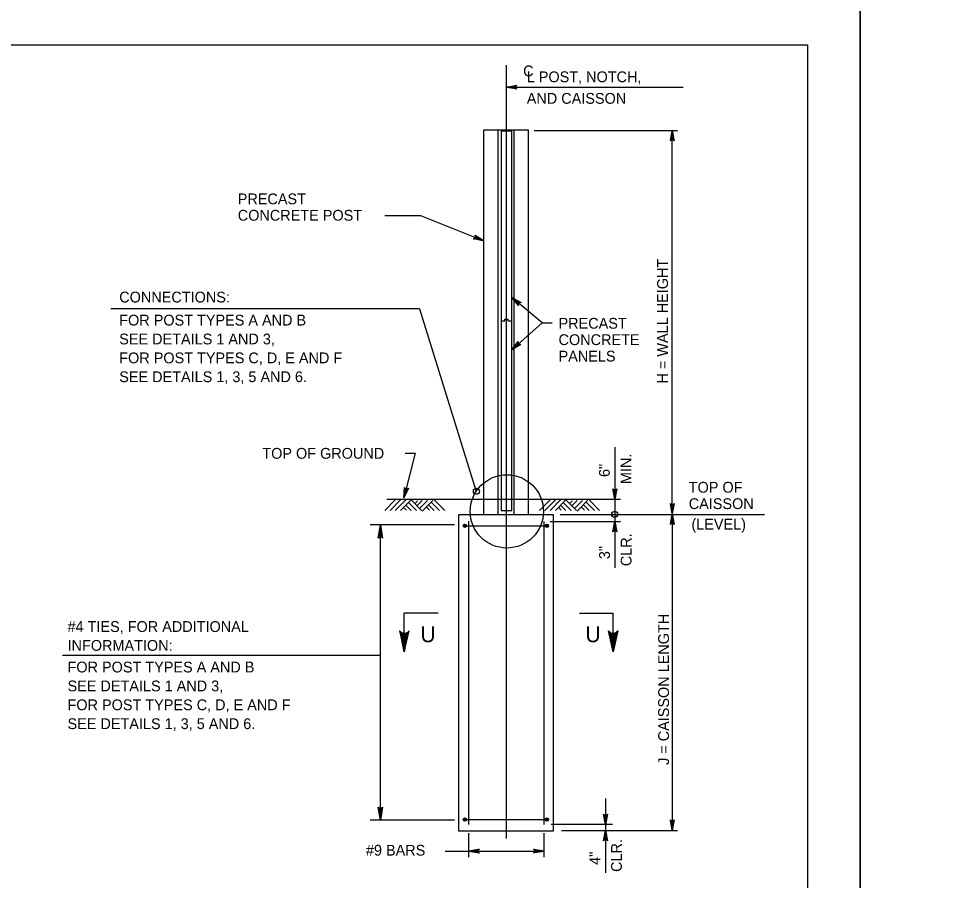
# Model space of a CAD drawing. Extents: x 3351 to 8430, y -3586 to 1457.
# Drawn here: x 4362.8 to 4626.6, y -3245.2 to -2999.8 of the extents above; entities that cross this region are included whole.
import ezdxf

# ---------------------------------------------------------------- set-up
doc = ezdxf.new("R2010")
doc.units = 0
for name, color, linetype in [('1', 7, 'Continuous'), ('2', 7, 'Continuous'), ('PLT-BNDY', 7, 'Continuous')]:
    doc.layers.add(name, color=color, linetype=linetype)

msp = doc.modelspace()

# ---------------------------------------------------------------- linework, layer by layer
at = {"layer": '1'}
for p, q in [((4501.69, -3233.31), (4501.69, -3013.08)), ((4501.69, -3019.37), (4551.98, -3019.37)), ((4495.23, -3141), (4495.23, -3031.53)), ((4495.23, -3031.53), (4507.98, -3031.53)), ((4499.36, -3141), (4499.36, -3031.53)), ((4503.86, -3141), (4503.86, -3031.53)), ((4507.98, -3141), (4507.98, -3031.53)), ((4509.59, -3031.69), (4550.39, -3031.69)), ((4548.88, -3140.87), (4548.88, -3031.69)), ((4467.06, -3055.93), (4477.25, -3055.93)), ((4477.25, -3055.93), (4495.23, -3063.11)), ((4511.82, -3086.41), (4503.19, -3079.21)), ((4476.92, -3082.48), (4389.09, -3082.48)), ((4476.92, -3082.48), (4493.06, -3134.45)), ((4500.19, -3085.91), (4500.19, -3103.66)), ((4501.21, -3085.91), (4501.21, -3085.43)), ((4501.21, -3085.43), (4502.17, -3085.43)), ((4502.17, -3085.91), (4502.17, -3085.43)), ((4503.19, -3103.35), (4503.19, -3085.91)), ((4511.82, -3086.41), (4503.19, -3094.16)), ((4511.82, -3086.41), (4514.72, -3086.41)), ((4532.5, -3121.82), (4532.5, -3141)), ((4475.72, -3123.53), (4472.5, -3136.33)), ((4472.82, -3123.53), (4475.72, -3123.53)), ((4467.05, -3139.89), (4470.05, -3136.89)), ((4467.68, -3136.68), (4534.14, -3136.68)), ((4468.55, -3139.89), (4471.55, -3136.89)), ((4470.05, -3139.89), (4473.05, -3136.89)), ((4471.55, -3139.89), (4474.55, -3136.89)), ((4473.22, -3139.83), (4472.4, -3139.01)), ((4474.55, -3139.89), (4473.05, -3138.39)), ((4476.05, -3139.89), (4473.8, -3137.64)), ((4477.55, -3139.89), (4474.55, -3136.89)), ((4476.4, -3137.12), (4475.58, -3137.95)), ((4477.73, -3137.07), (4476.22, -3138.57)), ((4479.23, -3137.07), (4476.97, -3139.32)), ((4480.73, -3137.07), (4477.72, -3140.07)), ((4479.81, -3139.83), (4478.99, -3139.01)), ((4481.14, -3139.89), (4479.64, -3138.39)), ((4482.64, -3139.89), (4480.39, -3137.64)), ((4484.14, -3139.89), (4481.14, -3136.89)), ((4511.11, -3139.86), (4514.11, -3136.86)), ((4512.61, -3139.86), (4515.61, -3136.86)), ((4514.11, -3139.86), (4517.11, -3136.86)), ((4515.61, -3139.86), (4518.61, -3136.86)), ((4517.28, -3139.8), (4516.46, -3138.98)), ((4518.61, -3139.86), (4517.11, -3138.36)), ((4520.11, -3139.86), (4517.86, -3137.61)), ((4521.61, -3139.86), (4518.61, -3136.86)), ((4520.46, -3137.09), (4519.64, -3137.92)), ((4521.79, -3137.04), (4520.29, -3138.54)), ((4523.29, -3137.04), (4521.04, -3139.29)), ((4524.79, -3137.04), (4521.79, -3140.04)), ((4523.87, -3139.8), (4523.05, -3138.98)), ((4525.2, -3139.86), (4523.7, -3138.36)), ((4526.7, -3139.86), (4524.45, -3137.61)), ((4528.2, -3139.86), (4525.2, -3136.86)), ((4515.07, -3141.12), (4488.07, -3141.12)), ((4488.07, -3141.12), (4488.07, -3231.12)), ((4515.07, -3231.12), (4515.07, -3141.12)), ((4516.94, -3141), (4575.13, -3141)), ((4532.5, -3141), (4532.5, -3143)), ((4548.88, -3140.87), (4548.88, -3230.97)), ((4486.92, -3144), (4462.89, -3144)), ((4465.22, -3147.74), (4465.81, -3143.94)), ((4465.81, -3143.94), (4465.38, -3147.54)), ((4465.64, -3147.41), (4465.81, -3143.94)), ((4465.81, -3228.12), (4465.81, -3143.94)), ((4465.81, -3143.94), (4466, -3147.41)), ((4466.27, -3147.53), (4465.81, -3143.94)), ((4465.81, -3143.94), (4466.44, -3147.73)), ((4465.81, -3143.94), (4465.82, -3147.41)), ((4489.87, -3144.22), (4513.2, -3144.22)), ((4491.01, -3229.33), (4491.01, -3142.94)), ((4512.37, -3229.33), (4512.37, -3143)), ((4514.1, -3143), (4534.14, -3143)), ((4532.5, -3143), (4532.5, -3156.19)), ((4465.38, -3147.54), (4465.22, -3147.74)), ((4465.38, -3147.54), (4465.64, -3147.41)), ((4465.64, -3147.41), (4466, -3147.41)), ((4466, -3147.41), (4466.27, -3147.53)), ((4466.44, -3147.73), (4466.27, -3147.53)), ((4482.21, -3169.1), (4472.56, -3169.1)), ((4472.56, -3180.1), (4472.56, -3169.1)), ((4522.44, -3169.1), (4532.09, -3169.1)), ((4532.09, -3180.1), (4532.09, -3169.1)), ((4465.81, -3181.14), (4375.38, -3181.14)), ((4529.87, -3221.92), (4529.87, -3229.33)), ((4465.81, -3228.12), (4465.17, -3224.33)), ((4465.17, -3224.33), (4465.35, -3224.52)), ((4465.61, -3224.65), (4465.35, -3224.52)), ((4465.35, -3224.52), (4465.81, -3228.12)), ((4465.81, -3228.12), (4465.61, -3224.65)), ((4465.97, -3224.65), (4465.61, -3224.65)), ((4465.81, -3228.12), (4465.79, -3224.65)), ((4466.4, -3224.32), (4465.81, -3228.12)), ((4465.81, -3228.12), (4466.24, -3224.51)), ((4465.97, -3224.65), (4465.81, -3228.12)), ((4466.24, -3224.51), (4465.97, -3224.65)), ((4466.24, -3224.51), (4466.4, -3224.32)), ((4486.92, -3228.08), (4462.89, -3228.08)), ((4489.87, -3227.9), (4513.2, -3227.9)), ((4488.07, -3231.12), (4515.07, -3231.12)), ((4531.87, -3229.33), (4514.37, -3229.33)), ((4517.37, -3230.97), (4550.39, -3230.97)), ((4529.87, -3229.33), (4529.87, -3230.97)), ((4529.87, -3230.97), (4529.87, -3243.06)), ((4491.01, -3238.56), (4491.01, -3231.77)), ((4512.37, -3238.56), (4512.37, -3231.77)), ((4484.22, -3236.85), (4491.01, -3236.85)), ((4491.01, -3236.85), (4512.37, -3236.85))]:
    msp.add_line(p, q, dxfattribs=at)
for points in [[(4501.69, -3019.37), (4504.68, -3018.81), (4504.45, -3018.97), (4504.33, -3019.17), (4504.29, -3019.37), (4504.33, -3019.57), (4504.45, -3019.77), (4504.68, -3019.93), (4501.69, -3019.37), (4504.45, -3019.77), (4504.33, -3019.57), (4501.69, -3019.37), (4504.29, -3019.37), (4504.33, -3019.17), (4501.69, -3019.37), (4504.45, -3018.97)], [(4503.19, -3049.61), (4503.19, -3031.91), (4500.19, -3031.91), (4500.19, -3050.4)], [(4548.88, -3031.69), (4549.44, -3034.67), (4549.36, -3034.55), (4549.28, -3034.44), (4549.18, -3034.38), (4549.08, -3034.32), (4548.98, -3034.3), (4548.88, -3034.29), (4548.78, -3034.3), (4548.68, -3034.32), (4548.58, -3034.38), (4548.48, -3034.44), (4548.4, -3034.55), (4548.32, -3034.67), (4548.88, -3031.69), (4548.4, -3034.55), (4548.48, -3034.44), (4548.88, -3031.69), (4548.58, -3034.38), (4548.68, -3034.32), (4548.88, -3031.69), (4548.78, -3034.3), (4548.88, -3034.29), (4548.88, -3031.69), (4548.98, -3034.3), (4549.08, -3034.32), (4548.88, -3031.69), (4549.18, -3034.38), (4549.28, -3034.44), (4548.88, -3031.69), (4549.36, -3034.55)], [(4500.19, -3050.09), (4500.19, -3067.91)], [(4503.19, -3085.91), (4503.19, -3049.34)], [(4495.23, -3063.11), (4492.25, -3062.52), (4492.39, -3062.49), (4492.53, -3062.46), (4492.62, -3062.39), (4492.71, -3062.32), (4492.76, -3062.23), (4492.82, -3062.14), (4492.84, -3062.04), (4492.86, -3061.95), (4492.84, -3061.83), (4492.82, -3061.72), (4492.75, -3061.6), (4492.67, -3061.48), (4495.23, -3063.11), (4492.75, -3061.6), (4492.82, -3061.72), (4495.23, -3063.11), (4492.84, -3061.83), (4492.86, -3061.95), (4495.23, -3063.11), (4492.84, -3062.04), (4492.82, -3062.14), (4495.23, -3063.11), (4492.76, -3062.23), (4492.71, -3062.32), (4495.23, -3063.11), (4492.62, -3062.39), (4492.53, -3062.46), (4495.23, -3063.11), (4492.39, -3062.49)], [(4500.2, -3067.91), (4500.19, -3067.91), (4500.19, -3085.91)], [(4503.19, -3079.21), (4505.84, -3080.69), (4505.56, -3080.67), (4505.34, -3080.74), (4505.19, -3080.88), (4505.09, -3081.05), (4505.05, -3081.28), (4505.12, -3081.55), (4503.19, -3079.21), (4505.05, -3081.28), (4505.09, -3081.05), (4503.19, -3079.21), (4505.19, -3080.88), (4505.34, -3080.74), (4503.19, -3079.21), (4505.56, -3080.67)], [(4500.19, -3085.91), (4501.21, -3085.91)], [(4502.17, -3085.91), (4503.19, -3085.91)], [(4503.19, -3094.16), (4505.04, -3091.75), (4504.97, -3092.02), (4505.02, -3092.25), (4505.13, -3092.42), (4505.29, -3092.55), (4505.51, -3092.62), (4505.79, -3092.59), (4503.19, -3094.16), (4505.51, -3092.62), (4505.29, -3092.55), (4503.19, -3094.16), (4505.13, -3092.42), (4505.02, -3092.25), (4503.19, -3094.16), (4504.97, -3092.02)], [(4500.19, -3139.91), (4503.19, -3139.91), (4503.19, -3103.35)], [(4500.19, -3103.66), (4500.19, -3139.91)], [(4472.5, -3136.33), (4472.69, -3133.3), (4472.74, -3133.43), (4472.79, -3133.56), (4472.87, -3133.64), (4472.95, -3133.72), (4473.04, -3133.76), (4473.14, -3133.8), (4473.24, -3133.81), (4473.34, -3133.82), (4473.45, -3133.79), (4473.56, -3133.75), (4473.67, -3133.66), (4473.77, -3133.57), (4472.5, -3136.33), (4473.67, -3133.66), (4473.56, -3133.75), (4472.5, -3136.33), (4473.45, -3133.79), (4473.34, -3133.82), (4472.5, -3136.33), (4473.24, -3133.81), (4473.14, -3133.8), (4472.5, -3136.33), (4473.04, -3133.76), (4472.95, -3133.72), (4472.5, -3136.33), (4472.87, -3133.64), (4472.79, -3133.56), (4472.5, -3136.33), (4472.74, -3133.43)], [(4532.5, -3136.68), (4531.94, -3133.7), (4532.02, -3133.81), (4532.1, -3133.93), (4532.2, -3133.99), (4532.3, -3134.05), (4532.4, -3134.06), (4532.5, -3134.08), (4532.6, -3134.06), (4532.7, -3134.05), (4532.8, -3133.99), (4532.9, -3133.93), (4532.98, -3133.81), (4533.06, -3133.7), (4532.5, -3136.68), (4532.98, -3133.81), (4532.9, -3133.93), (4532.5, -3136.68), (4532.8, -3133.99), (4532.7, -3134.05), (4532.5, -3136.68), (4532.6, -3134.06), (4532.5, -3134.08), (4532.5, -3136.68), (4532.4, -3134.06), (4532.3, -3134.05), (4532.5, -3136.68), (4532.2, -3133.99), (4532.1, -3133.93), (4532.5, -3136.68), (4532.02, -3133.81)], [(4548.88, -3140.87), (4548.32, -3137.89), (4548.4, -3138), (4548.48, -3138.12), (4548.58, -3138.18), (4548.68, -3138.23), (4548.78, -3138.25), (4548.88, -3138.27), (4548.98, -3138.25), (4549.08, -3138.23), (4549.18, -3138.18), (4549.28, -3138.12), (4549.36, -3138), (4549.44, -3137.89), (4548.88, -3140.87), (4549.36, -3138), (4549.28, -3138.12), (4548.88, -3140.87), (4549.18, -3138.18), (4549.08, -3138.23), (4548.88, -3140.87), (4548.98, -3138.25), (4548.88, -3138.27), (4548.88, -3140.87), (4548.78, -3138.25), (4548.68, -3138.23), (4548.88, -3140.87), (4548.58, -3138.18), (4548.48, -3138.12), (4548.88, -3140.87), (4548.4, -3138)], [(4548.88, -3140.87), (4549.44, -3143.85), (4549.36, -3143.74), (4549.28, -3143.62), (4549.18, -3143.56), (4549.08, -3143.5), (4548.98, -3143.49), (4548.88, -3143.47), (4548.78, -3143.49), (4548.68, -3143.5), (4548.58, -3143.56), (4548.48, -3143.62), (4548.4, -3143.74), (4548.32, -3143.85), (4548.88, -3140.87), (4548.4, -3143.74), (4548.48, -3143.62), (4548.88, -3140.87), (4548.58, -3143.56), (4548.68, -3143.5), (4548.88, -3140.87), (4548.78, -3143.49), (4548.88, -3143.47), (4548.88, -3140.87), (4548.98, -3143.49), (4549.08, -3143.5), (4548.88, -3140.87), (4549.18, -3143.56), (4549.28, -3143.62), (4548.88, -3140.87), (4549.36, -3143.74)], [(4532.5, -3143), (4533.06, -3145.98), (4532.98, -3145.86), (4532.9, -3145.75), (4532.8, -3145.69), (4532.7, -3145.63), (4532.6, -3145.61), (4532.5, -3145.6), (4532.4, -3145.61), (4532.3, -3145.63), (4532.2, -3145.69), (4532.1, -3145.75), (4532.02, -3145.86), (4531.94, -3145.98), (4532.5, -3143), (4532.02, -3145.86), (4532.1, -3145.75), (4532.5, -3143), (4532.2, -3145.69), (4532.3, -3145.63), (4532.5, -3143), (4532.4, -3145.61), (4532.5, -3145.6), (4532.5, -3143), (4532.6, -3145.61), (4532.7, -3145.63), (4532.5, -3143), (4532.8, -3145.69), (4532.9, -3145.75), (4532.5, -3143), (4532.98, -3145.86)], [(4472.56, -3180.1), (4473.98, -3174.15), (4473.78, -3174.37), (4473.59, -3174.6), (4473.35, -3174.72), (4473.11, -3174.84), (4472.87, -3174.87), (4472.63, -3174.9), (4472.39, -3174.86), (4472.15, -3174.83), (4471.91, -3174.71), (4471.67, -3174.59), (4471.48, -3174.35), (4471.29, -3174.12), (4472.56, -3180.1), (4471.48, -3174.35), (4471.67, -3174.59), (4472.56, -3180.1), (4471.91, -3174.71), (4472.15, -3174.83), (4472.56, -3180.1), (4472.39, -3174.86), (4472.63, -3174.9), (4472.56, -3180.1), (4472.87, -3174.87), (4473.11, -3174.84), (4472.56, -3180.1), (4473.35, -3174.72), (4473.59, -3174.6), (4472.56, -3180.1), (4473.78, -3174.37)], [(4532.09, -3180.1), (4530.68, -3174.15), (4530.87, -3174.37), (4531.06, -3174.6), (4531.31, -3174.72), (4531.55, -3174.84), (4531.79, -3174.87), (4532.03, -3174.9), (4532.27, -3174.86), (4532.51, -3174.83), (4532.75, -3174.71), (4532.98, -3174.59), (4533.17, -3174.35), (4533.36, -3174.12), (4532.09, -3180.1), (4533.17, -3174.35), (4532.98, -3174.59), (4532.09, -3180.1), (4532.75, -3174.71), (4532.51, -3174.83), (4532.09, -3180.1), (4532.27, -3174.86), (4532.03, -3174.9), (4532.09, -3180.1), (4531.79, -3174.87), (4531.55, -3174.84), (4532.09, -3180.1), (4531.31, -3174.72), (4531.06, -3174.6), (4532.09, -3180.1), (4530.87, -3174.37)], [(4529.87, -3229.33), (4529.31, -3226.35), (4529.39, -3226.46), (4529.47, -3226.58), (4529.57, -3226.64), (4529.67, -3226.69), (4529.77, -3226.71), (4529.87, -3226.73), (4529.97, -3226.71), (4530.07, -3226.69), (4530.17, -3226.64), (4530.27, -3226.58), (4530.35, -3226.46), (4530.43, -3226.35), (4529.87, -3229.33), (4530.35, -3226.46), (4530.27, -3226.58), (4529.87, -3229.33), (4530.17, -3226.64), (4530.07, -3226.69), (4529.87, -3229.33), (4529.97, -3226.71), (4529.87, -3226.73), (4529.87, -3229.33), (4529.77, -3226.71), (4529.67, -3226.69), (4529.87, -3229.33), (4529.57, -3226.64), (4529.47, -3226.58), (4529.87, -3229.33), (4529.39, -3226.46)], [(4548.88, -3230.97), (4548.32, -3227.99), (4548.4, -3228.1), (4548.48, -3228.22), (4548.58, -3228.28), (4548.68, -3228.34), (4548.78, -3228.35), (4548.88, -3228.37), (4548.98, -3228.35), (4549.08, -3228.34), (4549.18, -3228.28), (4549.28, -3228.22), (4549.36, -3228.1), (4549.44, -3227.99), (4548.88, -3230.97), (4549.36, -3228.1), (4549.28, -3228.22), (4548.88, -3230.97), (4549.18, -3228.28), (4549.08, -3228.34), (4548.88, -3230.97), (4548.98, -3228.35), (4548.88, -3228.37), (4548.88, -3230.97), (4548.78, -3228.35), (4548.68, -3228.34), (4548.88, -3230.97), (4548.58, -3228.28), (4548.48, -3228.22), (4548.88, -3230.97), (4548.4, -3228.1)], [(4529.87, -3230.97), (4530.43, -3233.95), (4530.35, -3233.83), (4530.27, -3233.72), (4530.17, -3233.66), (4530.07, -3233.6), (4529.97, -3233.58), (4529.87, -3233.57), (4529.77, -3233.58), (4529.67, -3233.6), (4529.57, -3233.66), (4529.47, -3233.72), (4529.39, -3233.83), (4529.31, -3233.95), (4529.87, -3230.97), (4529.39, -3233.83), (4529.47, -3233.72), (4529.87, -3230.97), (4529.57, -3233.66), (4529.67, -3233.6), (4529.87, -3230.97), (4529.77, -3233.58), (4529.87, -3233.57), (4529.87, -3230.97), (4529.97, -3233.58), (4530.07, -3233.6), (4529.87, -3230.97), (4530.17, -3233.66), (4530.27, -3233.72), (4529.87, -3230.97), (4530.35, -3233.83)], [(4491.01, -3236.85), (4494, -3236.29), (4493.88, -3236.37), (4493.77, -3236.45), (4493.71, -3236.55), (4493.65, -3236.65), (4493.63, -3236.75), (4493.61, -3236.85), (4493.63, -3236.95), (4493.65, -3237.05), (4493.71, -3237.15), (4493.77, -3237.25), (4493.88, -3237.33), (4494, -3237.41), (4491.01, -3236.85), (4493.88, -3237.33), (4493.77, -3237.25), (4491.01, -3236.85), (4493.71, -3237.15), (4493.65, -3237.05), (4491.01, -3236.85), (4493.63, -3236.95), (4493.61, -3236.85), (4491.01, -3236.85), (4493.63, -3236.75), (4493.65, -3236.65), (4491.01, -3236.85), (4493.71, -3236.55), (4493.77, -3236.45), (4491.01, -3236.85), (4493.88, -3236.37)], [(4512.37, -3236.85), (4509.39, -3237.41), (4509.51, -3237.33), (4509.62, -3237.25), (4509.68, -3237.15), (4509.74, -3237.05), (4509.76, -3236.95), (4509.77, -3236.85), (4509.76, -3236.75), (4509.74, -3236.65), (4509.68, -3236.55), (4509.62, -3236.45), (4509.51, -3236.37), (4509.39, -3236.29), (4512.37, -3236.85), (4509.51, -3236.37), (4509.62, -3236.45), (4512.37, -3236.85), (4509.68, -3236.55), (4509.74, -3236.65), (4512.37, -3236.85), (4509.76, -3236.75), (4509.77, -3236.85), (4512.37, -3236.85), (4509.76, -3236.95), (4509.74, -3237.05), (4512.37, -3236.85), (4509.68, -3237.15), (4509.62, -3237.25), (4512.37, -3236.85), (4509.51, -3237.33)]]:
    msp.add_lwpolyline(points, dxfattribs=at)
for centre, radius in [((4501.79, -3140.15), 10.43), ((4493.13, -3134.4), 0.868), ((4532.51, -3141), 0.868), ((4489.87, -3144.22), 0.468), ((4489.87, -3144.22), 0.354), ((4489.87, -3144.22), 0.253), ((4489.87, -3144.22), 0.143), ((4513.2, -3144.22), 0.468), ((4513.2, -3144.22), 0.354), ((4513.2, -3144.22), 0.253), ((4513.2, -3144.22), 0.143), ((4489.87, -3227.9), 0.468), ((4489.87, -3227.9), 0.354), ((4489.87, -3227.9), 0.253), ((4489.87, -3227.9), 0.143), ((4513.2, -3227.9), 0.468), ((4513.2, -3227.9), 0.354), ((4513.2, -3227.9), 0.253), ((4513.2, -3227.9), 0.143)]:
    msp.add_circle(centre, radius, dxfattribs=at)
at = {"layer": '2'}
for p, q in [((3801.34, -3007.31), (4587.34, -3007.31)), ((4587.34, -3007.31), (4587.34, -3571.31))]:
    msp.add_line(p, q, dxfattribs=at)
at = {"layer": 'PLT-BNDY'}
for points in [[(3761.34, -2992.31), (4602.34, -2992.31), (4602.34, -3586.31), (3761.34, -3586.31)], [(4602.34, -2992.31), (5443.34, -2992.31), (5443.34, -3586.31), (4602.34, -3586.31)]]:
    msp.add_lwpolyline(points, close=True, dxfattribs=at)

# ---------------------------------------------------------------- texts
at = {"layer": '1'}
for s, height, p in [('C', 3.07, (4506.43, -3016.26)), ('L POST, NOTCH, ', 3.072, (4507.46, -3017.94)), ('AND CAISSON', 3.072, (4507.46, -3024.08)), ('PRECAST', 3.072, (4425.22, -3052.7)), ('CONCRETE POST', 3.072, (4425.22, -3057.37)), ('CONNECTIONS: ', 3.072, (4391.49, -3080.66)), ('FOR POST TYPES A AND B', 3.072, (4391.49, -3087.22)), ('PRECAST', 3.072, (4516.51, -3088.12)), ('SEE DETAILS 1 AND 3,', 3.072, (4391.49, -3092.59)), ('CONCRETE', 3.072, (4516.51, -3092.79)), ('FOR POST TYPES C, D, E AND F', 3.072, (4391.49, -3097.97)), ('PANELS', 3.072, (4516.51, -3097.47)), ('SEE DETAILS 1, 3, 5 AND 6.', 3.072, (4391.49, -3103.34)), ('TOP OF GROUND', 3.072, (4432.21, -3125.15)), ('TOP OF', 3.072, (4553.56, -3134.81)), ('CAISSON', 3.072, (4553.56, -3139.48)), ('(LEVEL)', 3.072, (4554.32, -3145.3)), ('#4 TIES, FOR ADDITIONAL', 3.072, (4376.78, -3174.47)), ('U', 4.48, (4477.21, -3177.39)), ('U', 4.48, (4524.16, -3177.39)), ('INFORMATION: ', 3.072, (4376.78, -3179.84)), ('FOR POST TYPES A AND B', 3.072, (4376.78, -3186)), ('SEE DETAILS 1 AND 3,', 3.072, (4376.78, -3191.38)), ('FOR POST TYPES C, D, E AND F', 3.072, (4376.78, -3196.76)), ('SEE DETAILS 1, 3, 5 AND 6.', 3.072, (4376.78, -3202.13)), ('#9 BARS', 3.072, (4461.69, -3238.16))]:
    msp.add_text(s, height=height, dxfattribs=at).set_placement(p)
for s, p in [('H = WALL HEIGHT', (4547.64, -3103.72)), ('MIN.', (4537.23, -3132.36)), ('6"', (4531.09, -3130.35)), ('CLR.', (4537.27, -3155.74)), ('3"', (4531.12, -3153.74)), ('J = CAISSON LENGTH', (4547.94, -3212.34)), ('CLR.', (4534.52, -3242.8)), ('4"', (4528.37, -3240.79))]:
    msp.add_text(s, height=3.072, rotation=90, dxfattribs=at).set_placement(p)

doc.saveas('drawing.dxf')
